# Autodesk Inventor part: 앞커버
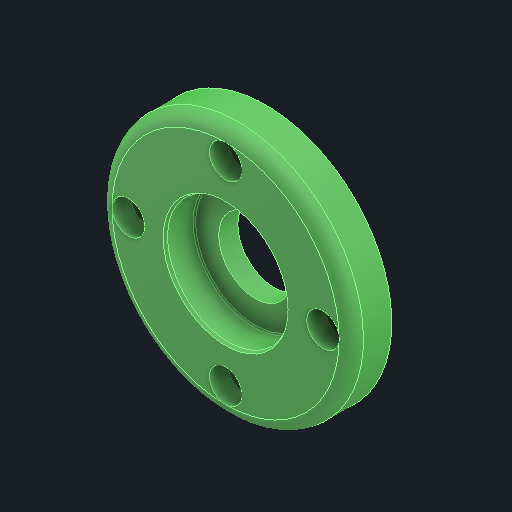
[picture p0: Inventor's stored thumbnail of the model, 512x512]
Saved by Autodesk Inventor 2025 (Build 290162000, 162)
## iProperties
Created: 2025-08
Part Number: 앞커버
Material: 알루미늄 6061
Document SubType Name: Modeling
Designer: infra027
Density: 2.71 g/cm^3
Appearance: 기본값
Author: jhkim
Sending System: Autodesk Inventor 2026
Preprocessor: ST-DEVELOPER v20.1
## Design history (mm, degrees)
feature "솔리드1"
node "솔리드2"
